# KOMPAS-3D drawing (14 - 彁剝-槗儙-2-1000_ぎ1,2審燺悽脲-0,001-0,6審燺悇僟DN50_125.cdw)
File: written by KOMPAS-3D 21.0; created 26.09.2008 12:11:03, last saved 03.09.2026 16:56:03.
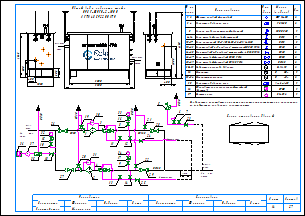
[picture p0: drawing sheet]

Sheets 1-2: A3, landscape

Document properties: Наименование: Макро:21; Автор: RaskoAdmin; Форматы листов документа: 2xA3; Полное имя файла: \\UR38nt01\Departments\КТО\КБ ПУРДГ\Заявки\Прайс-лист на типовые шкафы ГРПШ\ПРДГ_стандарт_20_03_2026\ПРДГ с РДГ(Н, В)\ПРДГ-ШУГО-2-1000_до1,2МПа_Рвых-0,001-0,6МПа_РДГ_DN50_125.cdw

Title block, sheet 1: Наименование: Пункт учета газа / ПУГ-Ш-400-Р / ЛГТИ.485922.001ТУ; designation: ЛГТИ.03.4411141; sheet number: 1; Количество листов документа: 2; organisation: ООО "ЭЛЬСТЕР Газэлектроника"; Форматы листов документа: A3; stored path: C:\Рабочие документы\Компас\ПУГ\Схема.cdw; Разработал: Устинов; Проверил: Кошкин; Утвердил: Кошкин
Title block, sheet 2: sheet number: 2; stored path: D:\Рабочие документы\Заявки\ПУРДГ\ПУРДГ-ШУЭО-2-100-Р 4411220.cdw; designation, second copy: ЛГТИ.03.4411141-

Views: Вид 1, Вид 2
Referenced files: wcvoit.frw
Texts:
  Normal
  Общий вид и габариты шкафа
  ПРДГ-ШУГО-2-1000
  Вход
  газа
  PDI
  Выход
  Р=     кПа
  DN125
  DN50
  DN20
  Импульс DN20
  ≥5DN
  HYSWLongFangSong
  Р=       МПа
  № на
  схеме
  Усл.
  обозн.
  Марка
  (модель)
  Кол.
  Фильтр газовый фланцевый
  ФГ 16-50
  Регулятор давления газа
  РДГ-50
  Клапан предохранительный сбросной
  КПС DN20
  Кран шаровой газовый латунный
  DN15
  Кран кнопочный VE-РАСКО-НЗ-1,6-G1/2-М20
  Кран шаровой "под приварку" штуцерный DN20 PN16
  Кран шаровой "под приварку" штуцерный п/п DN20 PN16
  Кран шаровой фланцевый DN50 PN16
  Кран шаровой фланцевый DN125 PN16
  Индикатор перепада давления
  Delta 15
  Манометр
  Манометр-напоромер
  0...     МПа
  0...     кПа
  Обогреватель газогорелочный шкафной
  (Эльтон")
  Счетчик газа
  Venio-A-15
  ОГШН
  BK-G1,6
  Схема открывания дверей
  Предприятие изготовитель может заменять комплектующие на аналогичные,
  не ухудшающие заявленных характеристик.
  Вход газа
  Выход газа
  logo-rasko-ge(1).png
  Должность
  Конструктор
  Фамилия
  Подпись
  Дата
  Согласовано
  Максимкин
  Лист
  Листов
  POLYLINE_STYLE_0.18_RGB_0_0_0
  POLYLINE_STYLE_0.50_RGB_0_0_0
  POLYLINE_STYLE_0.34_RGB_0_0_0
  PHANTOM_RGB_0_0_0_SC_1_THICK_0.18
  K5LT_THIN_RGB_0_0_0_THICK_0.18
  K5LT32769_RGB_0_0_0_THICK_0.18
  K5LT12_RGB_0_0_0_SC_1_THICK_0.18
  K5LT_DASHED_RGB_0_0_0_SC_1_THICK_0.18
  ACISOTGL_RGB_0_0_0_SC_0.8_THICK_0.25
  CONTINUOUS_RGB_0_127_31_THICK_0.3
  CONTINUOUS_RGB_0_0_255_THICK_0.35
  CONTINUOUS_RGB_255_0_0_THICK_0.35
  POLYLINE_STYLE_0.25_RGB_0_0_0
  CONTINUOUS_RGB_0_0_0_THICK_0.5
  POLYLINE_STYLE_0.35_RGB_0_0_255
  CONTINUOUS_RGB_0_0_0_THICK_0.4
  CONTINUOUS_RGB_0_0_0_THICK_0.35
  Без оформления
Dimensions and other numbers on the sheet: 1; 2; 3; 4; 5; 10; 27; 28; 29; 23; 8; 12; 19; 20; 21; 22; 25; 24; 30; 31; 15; 16; 32; 26; 6; 7; 11; 14; 13; 33; 9; 17; 34; 18; 35; 36; 37; 1, 2; 3, 4; 6-14; 15-17; 18-23; 24-25; 26-27; 28-29; 30-31; 33-34; 400; 1050; 500; 305; 1565; 1000; 4130; 3000; 3300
